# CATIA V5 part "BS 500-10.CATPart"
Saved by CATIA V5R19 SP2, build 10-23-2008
Part number: BS 500-10
Bounding box of the stored display mesh (mm): x -18.951 to 18.951, y -18.952 to 18.952, z 0 to 50
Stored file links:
  C:\Users\Bora\Desktop\3D Katı model\BS serisi\BS 500\BS 500-10.CATPart
  C:\Program Files\Dassault Systemes\B19\intel_a\reffiles\standard\MetricThickPitch.txt
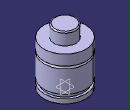
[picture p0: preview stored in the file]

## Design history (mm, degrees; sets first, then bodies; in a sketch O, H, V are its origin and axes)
Body1 (main body)
  Sketch1 on yz-plane, origin (0, 0, 0), H (0, 1, 0), V (0, 0, 1)
    point P1 (10, 49)
    point P3 (10, 49)
    point P5 (19, 29.5)
    point P6 (19, 27.5)
    point P9 (19, 29.5)
    point P14 (19, 27.5)
    line L1 (10, 49) -> (10, 39)
    arc A1 centre (9, 49) radius 1 from (10, 49) to (9, 50) ccw
    arc A2 centre (19, 28.5) radius 1 from (19, 29.5) to (19, 27.5) ccw
    line L2 (19, 0) -> (19, 4)
    line L3 (19, 29.5) -> (19, 39)
    line L4 (17, 7.5) -> (17, 4)
    line L5 (19, 7.5) -> (19, 27.5)
    line L6 (0, 50) -> (9, 50)
    point P15 (0, 50)
    line L7 (10, 39) -> (19, 39)
    line L8 (0, 0) -> (19, 0)
    line L9 (17, 7.5) -> (19, 7.5)
    line L10 (17, 4) -> (19, 4)
    coincidence: P15 V, P1 P3, P5 P9, P6 P14
    horizontal: L6 H, L7 H, L8 H, L9 H, L10 H
  Shaft1: profile Sketch1, axis Sketch1.V, angle 360
  Sketch2 on face of Shaft1 from Sketch1.L8, origin (0, 0, 0), H (1, 0, 0), V (0, -1, 0)
    point P1 (0, 0)
  Hole1: placed by Sketch2, at (0, 0, 0) direction (0, 0, 1), diameter 6.647, depth 4, threaded "M8", thread diameter 8, thread depth 4, pitch 1.25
